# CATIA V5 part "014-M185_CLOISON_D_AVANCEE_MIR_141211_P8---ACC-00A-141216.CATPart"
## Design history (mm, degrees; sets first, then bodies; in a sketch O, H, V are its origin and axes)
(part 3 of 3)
Body8 "SOFT MATERIAL"
  Body9 "soft material advanced"
    Body10
      ThickSurface2: BotOffset 0, Surface Split16, TopOffset 1.8
      Thickness11: Face face of ThickSurface2, Thickness 3
      Thickness12: Face face of ThickSurface2, Thickness -1.8
      Thickness13: Face face of ThickSurface2, Thickness 3
      Thickness14: Face face of ThickSurface2, Thickness -1.8
      Align3: SewingRemoveFace face of ThickSurface2, SplitPlane Extrapol121
      Align4: SewingRemoveFace face of ThickSurface2, SplitPlane Extrapol119
      Fillet99: radius 1.5, on edge [face of ThickSurface2 | face of ThickSurface2] (x2)
      Fillet100: radius 1.5, on edge [face of ThickSurface2 | face of ThickSurface2]
      Fillet101: radius 1.5, on edge [face of ThickSurface2 | face of ThickSurface2]
      Fillet102: radius 1.5, on edge [face of ThickSurface2 | face of ThickSurface2]
      Fillet103: radius 1.5, on edge [face of Fillet101 | face of ThickSurface2]
      Split83: SplitPlane Extrapol51
      Split84: SplitPlane Trim31
      Split85: SplitPlane Trim33
      Split86: SplitPlane Extrapol67
      Split87: SplitPlane Extrapol73
      Split88: SplitPlane Offset15
      Split89: SplitPlane Offset16
      Split90: SplitPlane Extrapol89
      Draft4: Angle 3, Neutral face of ThickSurface2, PullDir Line1, SupportToDraft face of Split84
      Draft5: Angle 3, Neutral face of ThickSurface2, PullDir Line1, SupportToDraft face of Split84
      Fillet104: radius 10, on edge [face of Split90 | face of Split90] (x2)
      Split91: SplitPlane Sweep45
      Fillet105: radius 10, on edge [face of Split91 | face of Split90]
      Draft6: Angle 3, Neutral face of ThickSurface2, PullDir Line1, SupportToDraft face of Split87
    Assemble1: tool Body10
    Split92: SplitPlane Fillet50
    Body11
      Solid4: linked copy from another document
      Split93: SplitPlane Extrapol206
      Split94: SplitPlane Fillet51
    Add5: tool Body11
    Body12
      Solid5: linked copy from another document
      Split95: SplitPlane Trim99
    Add6: tool Body12
    Split96: SplitPlane Offset18
    Draft7: Angle 3, Neutral face of ThickSurface2, PullDir Line1, SupportToDraft face of Split96
    Split97: SplitPlane Extrapol98
    Split98: SplitPlane Trim39
    Split99: SplitPlane Offset22
    Split100: SplitPlane Trim43
    Split101: SplitPlane Trim45
    Split102: SplitPlane Trim46
    Split103: SplitPlane Extrapol113
    Split104: SplitPlane Trim48
    Split105: SplitPlane Trim49
    Split106: SplitPlane Offset33
    Split107: SplitPlane Extrapol118
    Draft8: Angle 3, Neutral face of ThickSurface2, PullDir Line1, SupportToDraft face of Split96
    Draft9: Angle 3, Neutral face of ThickSurface2, PullDir Line1, SupportToDraft face of Split106
    Draft10: Angle 3, Neutral face of ThickSurface2, PullDir Line1, SupportToDraft face of Split98
    RemoveFace5: RemoveFaces face of Split92
    Thickness15: Face face of Split92, Thickness 0.5
    Fillet106: radius 5, on edge [face of Split92 | face of Split92]
    Split108: SplitPlane Join8
    RemoveFace6: RemoveFaces face of Split97
    Thickness16: Face face of Split97, Thickness 0.5
    Draft11: Angle 3, Neutral face of ThickSurface2, PullDir Line1, SupportToDraft face of Split97
    Fillet107: radius 5, on edge [face of Split97 | face of Split97]
    Draft12: Angle 3, Neutral face of ThickSurface2, PullDir Line1, SupportToDraft face of Split86
    Draft13: Angle 3, Neutral face of ThickSurface2, PullDir Line1, SupportToDraft face of Split98
    Draft14: Angle 3, Neutral face of ThickSurface2, PullDir Line1, SupportToDraft face of Split100
    Draft15: Angle 3, Neutral face of Split102, PullDir Line1, SupportToDraft face of Split101
    Draft16: Angle 3, Neutral face of ThickSurface2, PullDir Line1, SupportToDraft face of Split103
    Draft17: Angle 3, Neutral face of ThickSurface2, PullDir Line1, SupportToDraft face of Split102
    Draft18: Angle 3, Neutral face of ThickSurface2, PullDir Line1, SupportToDraft (face of Split105; face of Split85)
    Draft19: Angle 3, Neutral face of ThickSurface2, PullDir Line1, SupportToDraft face of Split104
    Split109: SplitPlane Join9
    Draft20: Angle 3, Neutral face of ThickSurface2, PullDir Line1, SupportToDraft (face of Split104; face of Split85)
    Body13
      Pad2: profile Sketch1, direction (0, 1, 0), length 400, thin wall 3
      Split110: SplitPlane Offset36
      Split111: SplitPlane Offset35
      Draft21: Angle 3, Neutral face of Split111, PullDir Line1, SupportToDraft (face of Pad2; face of Pad2)
      Draft22: Angle 3, Neutral face of Split111, PullDir Line1, SupportToDraft (face of Pad2; face of Pad2)
      Draft23: Angle 3, Neutral face of Split111, PullDir Line1, SupportToDraft (face of Pad2; face of Pad2)
      Draft24: Angle 3, Neutral face of Split111, PullDir Line1, SupportToDraft (face of Pad2; face of Pad2)
      Draft25: Angle 3, Neutral face of Split111, PullDir Line1, SupportToDraft (face of Pad2; face of Pad2)
      Draft26: Angle 3, Neutral face of Split111, PullDir Line1, SupportToDraft (face of Pad2; face of Pad2)
      Draft27: Angle 3, Neutral face of Split111, PullDir Line1, SupportToDraft (face of Pad2; face of Pad2)
      Draft28: Angle 3, Neutral face of Split111, PullDir Line1, SupportToDraft (face of Pad2; face of Pad2)
      Draft29: Angle 3, Neutral face of Split111, PullDir Line1, SupportToDraft (face of Pad2; face of Pad2)
      Draft30: Angle 3, Neutral face of Split111, PullDir Line1, SupportToDraft (face of Pad2; face of Pad2)
      Draft31: Angle 3, Neutral face of Split111, PullDir Line1, SupportToDraft (face of Pad2; face of Pad2)
      Draft32: Angle 3, Neutral face of Split111, PullDir Line1, SupportToDraft (face of Pad2; face of Pad2)
      Draft33: Angle 3, Neutral face of Split111, PullDir Line1, SupportToDraft (face of Pad2; face of Pad2)
      Draft34: Angle 3, Neutral face of Split111, PullDir Line1, SupportToDraft (face of Pad2; face of Pad2)
      Draft35: Angle 3, Neutral face of Split111, PullDir Line1, SupportToDraft (face of Pad2; face of Pad2)
      Draft36: Angle 3, Neutral face of Split111, PullDir Line1, SupportToDraft (face of Pad2; face of Pad2)
      Draft37: Angle 3, Neutral face of Split111, PullDir Line1, SupportToDraft (face of Pad2; face of Pad2)
      Draft38: Angle 3, Neutral face of Split111, PullDir Line1, SupportToDraft (face of Pad2; face of Pad2)
      Draft39: Angle 5, Neutral face of Split110, PullDir Line1, SupportToDraft face of Pad2
      Draft40: Angle 5, Neutral face of Split110, PullDir Line1, SupportToDraft (face of Pad2; face of Pad2; face of Pad2)
      Draft41: Angle 3, Neutral face of Split111, PullDir Line1, SupportToDraft face of Pad2
      Draft42: Angle 3, Neutral face of Split111, PullDir Line1, SupportToDraft face of Pad2
      Draft43: Angle 3, Neutral face of Split111, PullDir Line1, SupportToDraft face of Pad2
      Draft44: Angle 3, Neutral face of Split111, PullDir Line1, SupportToDraft face of Pad2
      Draft45: Angle 3, Neutral face of Split111, PullDir Line1, SupportToDraft face of Pad2
      Draft46: Angle 3, Neutral face of Split111, PullDir Line1, SupportToDraft face of Pad2
      Draft47: Angle 3, Neutral face of Split111, PullDir Line1, SupportToDraft (face of Pad2; face of Pad2; face of Pad2)
      Draft48: Angle 3, Neutral face of Split111, PullDir Line1, SupportToDraft (face of Pad2; face of Pad2; face of Pad2)
      Draft49: Angle 3, Neutral face of Split110, PullDir Line1, SupportToDraft (face of Pad2; face of Pad2; face of Pad2)
      Draft50: Angle 3, Neutral face of Split111, PullDir Line1, SupportToDraft (face of Pad2; face of Pad2; face of Pad2)
      Draft51: Angle 3, Neutral face of Split111, PullDir Line1, SupportToDraft (face of Pad2; face of Pad2; face of Pad2)
      Draft52: Angle 3, Neutral face of Split111, PullDir Line1, SupportToDraft (face of Pad2; face of Pad2; face of Pad2)
      Draft53: Angle 3, Neutral face of Split111, PullDir Line1, SupportToDraft (face of Pad2; face of Pad2; face of Pad2), deactivated
      Draft54: Angle 3, Neutral face of Split111, PullDir Line1, SupportToDraft (face of Pad2; face of Pad2; face of Pad2)
      Draft55: Angle 3, Neutral face of Split111, PullDir Line1, SupportToDraft (face of Pad2; face of Pad2; face of Pad2)
      Draft56: Angle 3, Neutral face of Split111, PullDir Line1, SupportToDraft (face of Pad2; face of Pad2; face of Pad2)
      Draft57: Angle 3, Neutral face of Split111, PullDir Line1, SupportToDraft (face of Pad2; face of Pad2; face of Pad2)
      Draft58: Angle 3, Neutral face of Split111, PullDir Line1, SupportToDraft (face of Pad2; face of Pad2; face of Pad2)
      Draft59: Angle 3, Neutral face of Split111, PullDir Line1, SupportToDraft (face of Pad2; face of Pad2; face of Pad2)
      Draft60: Angle 1.5, Neutral face of Split110, PullDir Line1, SupportToDraft (face of Pad2; face of Pad2; face of Pad2)
      Draft61: Angle 3, Neutral face of Split111, PullDir Line1, SupportToDraft (face of Pad2; face of Pad2; face of Pad2)
      Draft62: Angle 3, Neutral face of Split111, PullDir Line1, SupportToDraft (face of Pad2; face of Pad2; face of Pad2)
      Draft63: Angle 3, Neutral face of Split111, PullDir Line1, SupportToDraft (face of Pad2; face of Pad2; face of Pad2)
      Draft64: Angle 3, Neutral face of Split111, PullDir Line1, SupportToDraft (face of Pad2; face of Pad2; face of Pad2)
      Draft65: Angle 3, Neutral face of Split111, PullDir Line1, SupportToDraft (face of Pad2; face of Pad2; face of Pad2)
      Draft66: Angle 3, Neutral face of Split111, PullDir Line1, SupportToDraft (face of Pad2; face of Pad2; face of Pad2)
      Draft67: Angle 3, Neutral face of Split110, PullDir Line1, SupportToDraft (face of Pad2; face of Pad2; face of Pad2)
      Draft68: Angle 3, Neutral face of Split111, PullDir Line1, SupportToDraft (face of Pad2; face of Pad2; face of Pad2)
      Draft69: Angle 3, Neutral face of Split111, PullDir Line1, SupportToDraft (face of Pad2; face of Pad2; face of Pad2)
      Draft70: Angle 3, Neutral face of Split111, PullDir Line1, SupportToDraft (face of Pad2; face of Pad2; face of Pad2)
      Draft71: Angle 3, Neutral face of Split111, PullDir Line1, SupportToDraft (face of Pad2; face of Pad2; face of Pad2)
      Draft72: Angle 3, Neutral face of Split111, PullDir Line1, SupportToDraft (face of Pad2; face of Pad2; face of Pad2)
      Draft73: Angle 3, Neutral face of Split111, PullDir Line1, SupportToDraft (face of Pad2; face of Pad2; face of Pad2)
      Draft74: Angle 3, Neutral face of Split111, PullDir Line1, SupportToDraft (face of Pad2; face of Pad2; face of Pad2)
      Draft75: Angle 3, Neutral face of Split111, PullDir Line1, SupportToDraft (face of Pad2; face of Pad2; face of Pad2)
      Draft76: Angle 3, Neutral face of Split111, PullDir Line1, SupportToDraft (face of Pad2; face of Pad2; face of Pad2)
      Draft77: Angle 3, Neutral face of Split111, PullDir Line1, SupportToDraft (face of Pad2; face of Pad2; face of Pad2)
      Draft78: Angle 3, Neutral face of Split111, PullDir Line1, SupportToDraft (face of Pad2; face of Pad2; face of Pad2)
      Draft79: Angle 3, Neutral face of Split111, PullDir Line1, SupportToDraft (face of Pad2; face of Pad2; face of Pad2)
      Draft80: Angle 3, Neutral face of Split111, PullDir Line1, SupportToDraft (face of Pad2; face of Pad2; face of Pad2)
      Draft81: Angle 3, Neutral face of Split111, PullDir Line1, SupportToDraft (face of Pad2; face of Pad2; face of Pad2)
      Draft82: Angle 3, Neutral face of Split111, PullDir Line1, SupportToDraft (face of Pad2; face of Pad2; face of Pad2)
      Draft83: Angle 3, Neutral face of Split111, PullDir Line1, SupportToDraft (face of Pad2; face of Pad2; face of Pad2)
      Draft84: Angle 3, Neutral face of Split111, PullDir Line1, SupportToDraft (face of Pad2; face of Pad2; face of Pad2)
      Draft85: Angle 3, Neutral face of Split111, PullDir Line1, SupportToDraft (face of Pad2; face of Pad2; face of Pad2)
      Draft86: Angle 3, Neutral face of Split111, PullDir Line1, SupportToDraft (face of Pad2; face of Pad2; face of Pad2)
      Draft87: Angle 3, Neutral face of Split110, PullDir Line1, SupportToDraft (face of Pad2; face of Pad2; face of Pad2)
    Remove1: tool Body13
    Fillet108: radius 5, on edge [face of Split92 | face of Split94] (x2)
    Fillet109: radius 3, on edge [face of Split92 | face of Split92]
    Fillet110: radius 25, on edge [face of Split95 | face of Split95]
    Fillet111: radius 25, on edge [face of Split95 | face of Split95]
    Fillet112: radius 25, on edge [face of Split95 | face of Split95]
    Fillet113: radius 5, on edge [face of Split92 | face of Split95]
    Fillet114: radius 5, on edge [face of Split95 | face of Split92]
    Fillet115: radius 5, on edge [face of Split92 | face of Split92]
    Fillet116: radius 5, on edge [face of Split92 | face of Split92]
    Split112: SplitPlane Trim51
    Split113: SplitPlane Trim53
    Split114: SplitPlane Extrapol126, deactivated
    Thickness17: Face face of Split98, Thickness -2
    RemoveFace7: RemoveFaces face of Split98
    RemoveFace8: RemoveFaces face of Split87
    Draft88: Angle 5, Neutral face of ThickSurface2, PullDir Line1, SupportToDraft (face of Split87; face of Split99; face of Split99; face of Split98; face of Split98)
    RemoveFace9: RemoveFaces (face of Split87; face of Split87)
    Draft89: Angle 1.5, Neutral face of ThickSurface2, PullDir Line1, SupportToDraft (face of Split86; face of Split86; face of Split86; face of Split86; face of Split86; face of Split86; face of Split86)
    Draft90: Angle 3, Neutral face of ThickSurface2, PullDir Line1, SupportToDraft (face of Split97; face of Split107)
    RemoveFace10: RemoveFaces face of Split96
    RemoveFace11: RemoveFaces face of Split96
    Draft91: Angle 3, Neutral face of ThickSurface2, PullDir Line1, SupportToDraft (face of Split96; face of Split96)
    Draft92: Angle 3, Neutral face of ThickSurface2, PullDir Line1, SupportToDraft (face of Split84; face of Split104; face of Split84)
    Fillet117: radius 1.2, on edge [face of Pad2 | face of Pad2] (x34)
    Fillet118: radius 1.5, on edge [face of Pad2 | face of Pad2]
    RemoveFace12: RemoveFaces face of Split101
    Thickness18: Face face of Split99, Thickness 3
    Draft93: Angle 0, Neutral face of Split98, PullDir X axis, SupportToDraft face of Split99
    Thickness19: Face (face of Split86; face of Split86; face of Split86; face of Split86; face of Split86), Thickness 14
    Fillet119: radius 1.5, on edge [face of Pad2 | face of Pad2]
    Fillet120: radius 1.2, on edge [face of Pad2 | face of Pad2] (x4)
    Fillet121: radius 1.2, on edge [face of Pad2 | face of Pad2] (x10)
    Fillet122: radius 1.2, on edge [face of Pad2 | face of Pad2] (x2)
    Fillet123: radius 1.2, on edge [face of Pad2 | face of Pad2] (x2)
    Fillet124: radius 1.2, on edge [face of Pad2 | face of Pad2] (x2)
    Fillet125: radius 1.2, on edge [face of Pad2 | face of Pad2] (x2)
    Fillet126: radius 1.2, on edge [face of Pad2 | face of Pad2] (x2)
    Fillet127: radius 1.2, on edge [face of Pad2 | face of Pad2] (x2)
    Fillet128: radius 1.2, on edge [face of Pad2 | face of Pad2] (x2)
    Fillet129: radius 3, on edge [face of Split87 | face of Pad2]
    Fillet130: radius 1.2, on edge [face of Pad2 | face of Pad2]
    FaceFillet3: ConicRatio 0.5, Face1 face of Pad2, Face2 face of Pad2, Radius 0.5
    Fillet131: radius 1.2, on edge [face of Pad2 | face of Pad2] (x2)
    Fillet132: radius 1.2, on edge [face of Pad2 | face of Pad2] (x10)
    Fillet133: radius 3, on edge [face of Split86 | face of Split86]
    Fillet134: radius 1.2, on edge [face of Pad2 | face of Pad2] (x2)
    Fillet135: radius 1.2, on edge [face of Pad2 | face of Pad2] (x12)
    Fillet136: radius 1.2, on edge [face of Pad2 | face of Pad2] (x2)
    Fillet137: radius 1.2, on edge [face of Pad2 | face of Pad2] (x10)
    Fillet138: radius 1.2, on edge [face of Pad2 | face of Pad2] (x8)
    Fillet139: radius 1.2, on edge [face of Pad2 | face of Pad2] (x2)
    Draft94: Angle 3, Neutral face of ThickSurface2, PullDir Line1, SupportToDraft (face of Split85; face of Split85)
    Fillet140: radius 2, on edge [face of Split85 | face of Split85] (x2)
    Fillet141: radius 1.2, on edge [face of Pad2 | face of Pad2] (x2)
    Fillet142: radius 4.5, on edge [face of Split84 | face of Split105]
    FaceFillet4: ConicRatio 0.5, Face1 face of Split84, Face2 face of Split84, Radius 15
    Fillet143: radius 1.5, on edge [face of Split84 | face of Pad2] (x4); edge [face of Pad2 | face of Split84] (x3)
    FaceFillet5: ConicRatio 0.5, Face1 face of Split103, Face2 face of Split89, Radius 2
    Fillet144: radius 4, on edge [face of Split89 | face of Pad2], deactivated
    Fillet145: radius 1.5, on edge [face of Pad2 | face of Split83] (x9); edge [face of Split83 | face of Pad2] (x9)
    Draft95: Angle 3, Neutral face of ThickSurface2, PullDir Line1, SupportToDraft (face of Pad2; face of Pad2)
    Fillet146: radius 1.5, on edge [face of Pad2 | face of Pad2] (x2)
    Fillet147: radius 1.5, on edge [face of Pad2 | face of Split83]; edge [face of Split83 | face of Pad2]
    Fillet148: radius 1, on edge [face of Split114 | face of Split114] (x2), deactivated
    Fillet149: radius 1, on edge [face of Split112 | face of Split112] (x2)
    Fillet150: radius 1, on edge [face of ThickSurface2 | face of Split112]
    Fillet151: radius 1, on edge [face of Split114 | face of ThickSurface2], deactivated
    Fillet152: radius 1.5, on edge [face of Pad2 | face of Split83] (x2); edge [face of Split83 | face of Pad2] (x2)
    Fillet153: radius 5, on edge [face of Split83 | face of Split88]; edge [face of Split101 | face of Split88]
    Fillet154: radius 5, on edge [face of Pad2 | face of Split101]
    Fillet155: radius 1.5, on edge [face of Split102 | face of Pad2] (x2); edge [face of Pad2 | face of Split102] (x2)
    Fillet156: radius 5, on edge [face of Split102 | face of Pad2]
    Fillet157: radius 5, on edge [face of Pad2 | face of Split102]
    Fillet158: radius 1.5, on edge [face of Split102 | face of Pad2]; edge [face of Pad2 | face of Split102] (x3); edge [face of Split102 | face of Split102]
    Fillet159: radius 1.5, on edge [face of Split100 | face of Pad2] (x2)
    Fillet160: radius 1, on edge [face of Split100 | face of ThickSurface2]
    Fillet161: radius 1.5, on edge [face of Split98 | face of Pad2] (x6); edge [face of Pad2 | face of Split98] (x5)
    Fillet162: radius 10, on edge [face of Pad2 | face of Split98]
    Fillet163: radius 1.5, on edge [face of Split98 | face of Pad2] (x2); edge [face of Split99 | face of Pad2] (x2)
    Fillet164: radius 5, on edge [face of Split98 | face of Split99]
    Fillet165: radius 10, on edge [face of Split99 | face of Split87]
    Fillet166: radius 5, on edge [face of Pad2 | face of Split87]
    Fillet167: radius 5, on edge [face of Split86 | face of Split87]; edge [face of Pad2 | face of Split87]
    Fillet168: radius 1.5, on edge [face of Split86 | face of Pad2] (x9)
    RemoveFace13: RemoveFaces (face of Pad2; face of Split86; face of Split86; face of ThickSurface2)
    Fillet169: radius 2, on edge [face of Split86 | face of Pad2]
    Fillet170: radius 5, on edge [face of Split86 | face of Split86]
    Fillet171: radius 2, on edge [face of Split86 | face of Pad2]
    Draft96: Angle 3, Neutral face of ThickSurface2, PullDir Line1, SupportToDraft face of Split97
    Draft97: Angle 3, Neutral face of ThickSurface2, PullDir Line1, SupportToDraft face of Pad2
    Fillet172: radius 1.5, on edge [face of Split97 | face of Pad2] (x2)
    Fillet173: radius 5, on edge [face of Split97 | face of Split106]
    Fillet174: radius 1.5, on edge [face of Split106 | face of Pad2]; edge [face of Pad2 | face of Split106]
    Fillet175: radius 5, on edge [face of Split106 | face of Pad2]
    Fillet176: radius 10, on edge [face of Split107 | face of Split96]
    Fillet177: radius 10, on edge [face of Split107 | face of Split97]
    Fillet178: radius 1.5, on edge [face of Pad2 | face of Split96] (x2); edge [face of Split96 | face of Pad2] (x6)
    Fillet179: radius 5, on edge [face of Split96 | face of Split96]
    Fillet180: radius 10, on edge [face of Split96 | face of Pad2]
    Fillet181: radius 1.5, on edge [face of Split96 | face of Pad2]
    Fillet182: radius 5, on edge [face of Split90 | face of ThickSurface2]; edge [face of ThickSurface2 | face of Split96]
    Fillet183: radius 1.5, on edge [face of Pad2 | face of Split96]; edge [face of Split96 | face of Pad2]; edge [face of Split90 | face of Pad2] (x7); edge [face of Pad2 | face of Split90] (x5)
    Fillet184: radius 3, on edge [face of Split104 | face of Split91]
    Fillet185: radius 1.5, on edge [face of Pad2 | face of Split104] (x2)
    Fillet186: radius 5, on edge [face of Split104 | face of Split104]
    Fillet187: radius 4, on edge [face of Split104 | face of Split104]
    Fillet188: radius 1.5, on edge [face of Split84 | face of Pad2]; edge [face of Split104 | face of Pad2]
    Fillet189: radius 1.5, on edge [face of Split84 | face of Pad2] (x2)
    Fillet190: radius 1.5, on edge [face of Split105 | face of Pad2]
    Fillet191: radius 1.5, on edge [face of Pad2 | face of Split105]
    Fillet192: radius 4, on edge [face of Split84 | face of Pad2]
    Fillet193: radius 5, on edge [face of Split85 | face of Pad2]
    Fillet194: radius 1.5, on edge [face of Split85 | face of Split105]
    Fillet195: radius 1.5, on edge [face of Split103 | face of Pad2] (x2); edge [face of Pad2 | face of Split103]
    Fillet196: radius 1.5, on edge [face of Split103 | face of Pad2]; edge [face of Pad2 | face of Split103]
    RemoveFace14: RemoveFaces (face of Split91; face of Split91)
    RemoveFace15: RemoveFaces (face of Split86; face of Fillet133)
    Fillet197: radius 0.95, on edge [face of Split91 | face of ThickSurface2]
    Fillet198: radius 1, on edge [face of Split113 | face of Split113] (x2)
    Fillet199: radius 1, on edge [face of Split113 | face of ThickSurface2]
    Fillet200: radius 5, on edge [face of Split89 | face of Split83]
    Fillet201: radius 0.8, on edge [face of ThickSurface2 | face of Split83] (x3)
    Fillet202: radius 1.5, on edge [face of Fillet119 | face of Split102]
    Fillet203: radius 1, on edge [face of ThickSurface2 | face of Split102]
    Fillet204: radius 1, on edge [face of Pad2 | face of ThickSurface2]
    RemoveFace16: RemoveFaces (face of Split86; face of Fillet133), deactivated
    Fillet205: radius 1, on edge [face of Split86 | face of ThickSurface2]; edge [face of Split90 | face of ThickSurface2], deactivated
    Thickness20: Face face of Split92, Thickness 2.1
    Body14
      CloseSurface1: CloseElement Trim129
      CloseSurface2: CloseElement Trim130
    Add7: tool Body14
    Thickness21: Face (face of Split92; face of Split95; face of Fillet112; face of Split94), Thickness 2.1
    Thickness22: Face face of Thickness21, Thickness 2.1
    Thickness23: Face (face of CloseSurface2; face of CloseSurface2), Thickness 3
    Split115: SplitPlane Join20
    Fillet206: radius 3, on edge [face of Split115 | face of Split115]
    Draft98: Angle -3, Neutral Offset92, PullDir Line1, SupportToDraft (face of Split108; face of Split109; face of Split109)
  Add8: tool Body9
  Split116: SplitPlane Fillet36
  Fillet207: radius 8, on edge [face of Split115 | face of Split116]; edge [face of Split116 | face of Split116] (x2)
  Fillet208: radius 10, on edge [face of Split115 | face of Split116]; edge [face of Split116 | face of Split116] (x2)
  Sketch7 on Plane12, origin (0, 255.047, 0), H (-1, 0, 0), V (0, 0, 1)
    line L1 (930.7962, 72.0965) -> (907.5986, 72.0965)
    line L2 (907.5986, 72.0965) -> (907.5986, 42.9347)
    line L3 (907.5986, 42.9347) -> (930.7962, 42.9347)
    line L4 (930.7962, 42.9347) -> (930.7962, 72.0965)
    reference projected point E1 (927.7962, 52.871) from vertex of DatumPoint1
    reference projected point E2 (920.246, 69.0965) from vertex of DatumPoint2
    reference projected point E3 (910.5986, 52.4066) from vertex of DatumPoint3
    reference projected point E4 (913.024, 45.9347) from vertex of DatumPoint4
    distance L4 E1 = 3
    distance L1 E2 = 3
    distance L2 E3 = 3
    distance L3 E4 = 3
    horizontal: L1 H, L3 H
    vertical: L2 V, L4 V
  Pocket2: profile Sketch7, direction (0, 1, 0), length 400
  RemoveFace17: RemoveFaces (face of Fillet138; face of Pad2; face of Fillet138; face of Fillet197; face of Fillet197; face of Fillet197)
  Draft99: Angle 3, Neutral face of ThickSurface2, PullDir Line1, SupportToDraft (face of Pocket2; face of Pocket2 from Sketch7.L1; face of Pocket2 from Sketch7.L4; face of Pocket2 from Sketch7.L3; face of Pocket2 from Sketch7.L4)
  Fillet209: radius 3, on edge [face of Pocket2 from Sketch7.L4 | face of Pocket2 from Sketch7.L1]; edge [face of Pocket2 from Sketch7.L3 | face of Pocket2 from Sketch7.L4]; edge [face of Pocket2 from Sketch7.L3 | face of Pocket2]; edge [face of Pocket2 from Sketch7.L1 | face of Pocket2]
  Fillet210: radius 1, on edge [face of Pocket2 | face of ThickSurface2]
